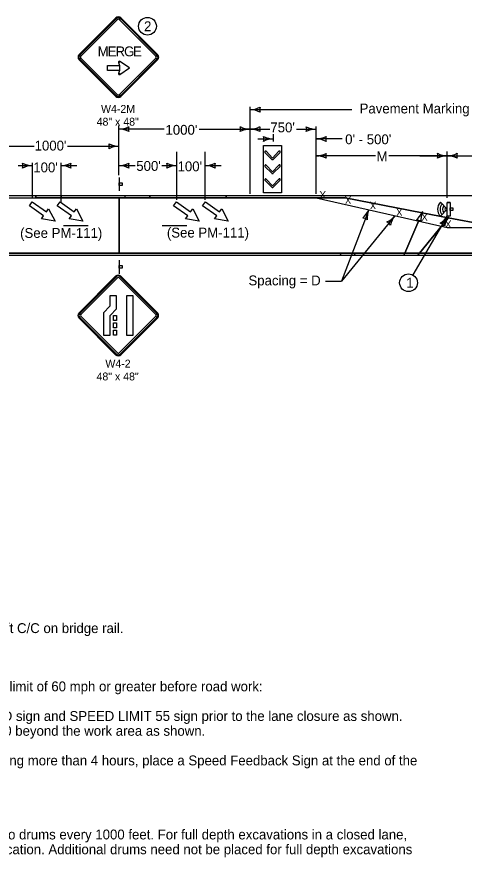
# Model space of a CAD drawing. Extents: x 10133 to 2270741, y 5363 to 1733450.
# Drawn here: x 25567 to 26474, y 5452 to 7155 of the extents above; entities that cross this region are included whole.
import ezdxf

# ---------------------------------------------------------------- set-up
doc = ezdxf.new("R2010")
doc.units = 0
for name, color, linetype in [('dsnNonPlotable', 7, 'Continuous'), ('dsnShtPlotShapeBatchPrint', 7, 'Continuous'), ('dsnStdBlockModified', 7, 'Continuous'), ('dsnStdBorder', 7, 'Continuous'), ('dsnStdNote', 7, 'Continuous'), ('dsnStdTable', 7, 'Continuous'), ('Level 12', 7, 'Continuous'), ('Level 2', 7, 'Continuous')]:
    doc.layers.add(name, color=color, linetype=linetype)

msp = doc.modelspace()

# ---------------------------------------------------------------- linework, layer by layer
at = {"layer": 'dsnNonPlotable'}
for p, q in [((24565.8, 6787.8), (26174.1, 6787.8)), ((25592.9, 6771.4), (25598.6, 6779.6)), ((25598.6, 6779.6), (25627.3, 6759.5)), ((25649.4, 6771.4), (25655.2, 6779.6)), ((25655.2, 6779.6), (25683.8, 6759.5)), ((25885.2, 6771.4), (25890.9, 6779.6)), ((25890.9, 6779.6), (25919.6, 6759.5)), ((25943.9, 6771.4), (25949.7, 6779.6)), ((25949.7, 6779.6), (25978.3, 6759.5)), ((26174.1, 6787.8), (26439.8, 6728.1)), ((25621.5, 6751.3), (25592.9, 6771.4)), ((25627.3, 6759.5), (25631.6, 6765.6)), ((25631.6, 6765.6), (25644.9, 6741)), ((25678.1, 6751.3), (25649.4, 6771.4)), ((25683.8, 6759.5), (25688.1, 6765.6)), ((25688.1, 6765.6), (25701.4, 6741)), ((25913.8, 6751.3), (25885.2, 6771.4)), ((25919.6, 6759.5), (25923.9, 6765.6)), ((25923.9, 6765.6), (25937.2, 6741)), ((25972.6, 6751.3), (25943.9, 6771.4)), ((25978.3, 6759.5), (25982.6, 6765.6)), ((25982.6, 6765.6), (25995.9, 6741)), ((25617.2, 6745.1), (25621.5, 6751.3)), ((25644.9, 6741), (25617.2, 6745.1)), ((25673.8, 6745.1), (25678.1, 6751.3)), ((25701.4, 6741), (25673.8, 6745.1)), ((25909.5, 6745.1), (25913.8, 6751.3)), ((25937.2, 6741), (25909.5, 6745.1)), ((25968.3, 6745.1), (25972.6, 6751.3)), ((25995.9, 6741), (25968.3, 6745.1)), ((26439.8, 6728.1), (26588, 6728.1)), ((24557.8, 6675.8), (26586.2, 6675.8))]:
    msp.add_line(p, q, dxfattribs=at)
for points in [[(25662, 6731.8), (25712, 6731.8)], [(25662, 6731.8), (25712, 6731.8)], [(25862, 6731.8), (25912, 6731.8)]]:
    msp.add_lwpolyline(points, dxfattribs=at)
at = {"layer": 'dsnShtPlotShapeBatchPrint'}
msp.add_circle((25832.2, 7135.5), 18, dxfattribs=at)
at = {"layer": 'dsnStdBlockModified'}
for p, q in [((26425.7, 6778.9), (26439.8, 6764.7)), ((26445.5, 6778.5), (26439.8, 6778.5)), ((26439.8, 6764.7), (26425.7, 6750.6)), ((26445.5, 6751), (26439.8, 6751))]:
    msp.add_line(p, q, dxfattribs=at)
for radius, start, end in [(20.3, 135.88, 224.0313), (15.3, 136.1665, 223.7159), (10.3, 136.7294, 223.0963), (5.32, 138.7005, 221.2995)]:
    msp.add_arc((26440.3, 6764.7), radius, start, end, dxfattribs=at)
at = {"layer": 'dsnStdBorder'}
for p, q in [((25767.9, 7152.4), (25693.7, 7078.2)), ((25769.3, 7151.1), (25771.5, 7148.9)), ((25775, 7148.9), (25777.2, 7151.1)), ((25852.8, 7078.2), (25778.5, 7152.4)), ((25693.7, 7067.6), (25767.9, 6993.3)), ((25697.2, 7074.7), (25695, 7076.9)), ((25695, 7068.9), (25697.2, 7071.1)), ((25778.5, 6993.3), (25852.8, 7067.6)), ((25851.5, 7076.9), (25849.2, 7074.7)), ((25849.2, 7071.1), (25851.5, 7068.9)), ((25773.3, 7061.9), (25775.3, 7062.6)), ((25775.3, 7062.6), (25776.3, 7064.3)), ((25775.3, 7039.5), (25773.3, 7040.1)), ((25776.3, 7037.7), (25775.3, 7039.5)), ((25771.5, 6996.9), (25769.3, 6994.7)), ((25777.2, 6994.7), (25775, 6996.9)), ((26086.8, 6865.8), (26100.9, 6879.9)), ((26086.8, 6837.6), (26100.9, 6851.7)), ((25775, 6829.3), (25775, 6801.8)), ((26086.8, 6809.5), (26100.9, 6823.6)), ((26445.5, 6778.5), (26445.5, 6751)), ((25775, 6661.8), (25775, 6634.3)), ((25693.5, 6555), (25767.7, 6629.3)), ((25767.7, 6629.3), (25693.5, 6555)), ((25694.8, 6553.7), (25769.1, 6628)), ((25771.3, 6625.8), (25697, 6551.5)), ((25767.7, 6629.3), (25767.7, 6629.3)), ((25771.3, 6625.8), (25771.3, 6625.8)), ((25849, 6551.5), (25774.8, 6625.8)), ((25777, 6628), (25851.3, 6553.7)), ((25778.3, 6629.3), (25852.6, 6555)), ((25852.6, 6555), (25778.3, 6629.3)), ((25767.7, 6470.2), (25693.5, 6544.4)), ((25693.5, 6544.4), (25767.7, 6470.2)), ((25769.1, 6471.5), (25694.8, 6545.8)), ((25697, 6548), (25771.3, 6473.7)), ((25774.8, 6473.7), (25849, 6548)), ((25851.3, 6545.8), (25777, 6471.5)), ((25852.6, 6544.4), (25778.3, 6470.2)), ((25778.3, 6470.2), (25852.6, 6544.4))]:
    msp.add_line(p, q, dxfattribs=at)
for points in [[(25769.3, 7151.1), (25695, 7076.9), (25697.2, 7074.7), (25771.5, 7148.9), (25769.3, 7151.1)], [(25851.5, 7076.9), (25777.2, 7151.1), (25775, 7148.9), (25849.2, 7074.7), (25851.5, 7076.9)], [(25695, 7068.9), (25769.3, 6994.7), (25771.5, 6996.9), (25697.2, 7071.1), (25695, 7068.9)], [(25777.2, 6994.7), (25851.5, 7068.9), (25849.2, 7071.1), (25775, 6996.9), (25777.2, 6994.7)], [(25750.9, 7046), (25750.9, 7056), (25775.3, 7056), (25775.3, 7046), (25750.9, 7046)], [(25795.6, 7051), (25776.3, 7064.3), (25775.3, 7062.6), (25773.3, 7061.9), (25775.3, 7056), (25775.3, 7046), (25773.3, 7040.1), (25775.3, 7039.5), (25776.3, 7037.7), (25795.6, 7051)], [(26104, 6894), (26104, 6798), (26067.3, 6798), (26067.3, 6894)], [(25775.1, 6812.9), (25775.1, 6818.5), (25780.8, 6818.5), (25780.8, 6812.9)], [(26439.8, 6751), (26439.8, 6778.5), (26445.5, 6778.5), (26445.5, 6751)], [(26445.5, 6762), (26445.5, 6767.7), (26451.1, 6767.7), (26451.1, 6762)], [(25775.1, 6645.4), (25775.1, 6651), (25780.8, 6651), (25780.8, 6645.4)], [(25756, 6568.6), (25742.8, 6555.3), (25742.8, 6509.7), (25756.3, 6509.7), (25756.3, 6549.7), (25769.5, 6563), (25769.5, 6589.7), (25756, 6589.7)], [(25789.8, 6589.7), (25789.8, 6509.7), (25803.3, 6509.7), (25803.3, 6589.7)], [(25763.5, 6549.7), (25769.5, 6549.7), (25769.5, 6539.7), (25763.5, 6539.7)], [(25763.5, 6534.7), (25769.5, 6534.7), (25769.5, 6524.7), (25763.5, 6524.7)], [(25763.5, 6519.7), (25769.5, 6519.7), (25769.5, 6509.7), (25763.5, 6509.7)]]:
    msp.add_lwpolyline(points, close=True, dxfattribs=at)
for points in [[(26070.3, 6880), (26070.3, 6879.9), (26084.4, 6865.8), (26084.4, 6865.8)], [(26098.6, 6882.3), (26098.5, 6882.2), (26085.6, 6868.6), (26072.7, 6882.2)], [(26070.3, 6851.7), (26070.3, 6851.7), (26084.4, 6837.6), (26084.4, 6837.6)], [(26098.6, 6854), (26098.5, 6854), (26085.6, 6840.4), (26072.7, 6854)], [(26070.3, 6823.7), (26070.3, 6823.6), (26084.4, 6809.5), (26084.4, 6809.5)], [(26098.6, 6826), (26098.5, 6825.9), (26085.6, 6812.3), (26072.7, 6825.9)], [(25769.1, 6628), (25694.8, 6553.7)], [(25771.3, 6625.8), (25697, 6551.5)], [(25849, 6551.5), (25774.8, 6625.8)], [(25851.3, 6553.7), (25777, 6628)], [(25694.8, 6545.8), (25769.1, 6471.5)], [(25697, 6548), (25771.3, 6473.7)], [(25774.8, 6473.7), (25849, 6548)], [(25777, 6471.5), (25851.3, 6545.8)]]:
    msp.add_lwpolyline(points, dxfattribs=at)
for centre, radius, start, end in [((25773.2, 7147.1), 7.5, 45, 134.9997), ((25773.2, 7147.1), 5.62, 45, 134.9997), ((25773.2, 7147.1), 2.5, 45, 134.9997), ((25699, 7072.9), 7.5, 134.9997, 225), ((25699, 7072.9), 5.62, 134.9997, 225), ((25699, 7072.9), 2.5, 134.9997, 225), ((25847.5, 7072.9), 2.5, 315.0002, 44.9998), ((25847.5, 7072.9), 5.62, 315.0002, 44.9998), ((25847.5, 7072.9), 7.5, 315.0002, 44.9998), ((25775.3, 7062.6), 2.03, 57.6877, 198.5814), ((25775.3, 7039.5), 2.03, 161.4183, 302.3126), ((25773.2, 6998.6), 2.5, 225, 315.0002), ((25773.2, 6998.6), 7.5, 225, 315.0002), ((25773.2, 6998.6), 5.62, 225, 315.0002), ((26071.5, 6881.1), 1.65, 42.6398, 223.799), ((26099.7, 6881.1), 1.65, 314.719, 134.9025), ((26085.6, 6867), 1.65, 225.3902, 315.8384), ((26071.5, 6852.9), 1.65, 42.6398, 223.799), ((26099.7, 6852.9), 1.65, 314.719, 134.9025), ((26071.5, 6824.8), 1.65, 42.6398, 223.799), ((26085.6, 6838.7), 1.65, 225.3902, 315.8384), ((26099.7, 6824.8), 1.65, 314.719, 134.9025), ((26085.6, 6810.7), 1.65, 225.3902, 315.8384), ((25773, 6624), 7.5, 45.0003, 135), ((25773, 6624), 7.5, 45.0003, 135), ((25773, 6624), 5.63, 45.0003, 135), ((25773, 6624), 5.63, 45.0003, 135), ((25773, 6624), 2.5, 45.0003, 135), ((25773, 6624), 2.5, 45.0003, 135), ((25698.8, 6549.7), 7.5, 135.0002, 224.9998), ((25698.8, 6549.7), 7.5, 135.0002, 224.9998), ((25847.3, 6549.7), 7.5, 315, 45.0003), ((25847.3, 6549.7), 7.5, 315, 45.0003), ((25698.8, 6549.7), 5.63, 135.0002, 224.9998), ((25698.8, 6549.7), 5.63, 135.0002, 224.9998), ((25698.8, 6549.7), 2.5, 135.0002, 224.9998), ((25698.8, 6549.7), 2.5, 135.0002, 224.9998), ((25847.3, 6549.7), 2.5, 315, 45.0003), ((25847.3, 6549.7), 2.5, 315, 45.0003), ((25847.3, 6549.7), 5.63, 315, 45.0003), ((25847.3, 6549.7), 5.63, 315, 45.0003), ((25773, 6475.5), 7.5, 224.9998, 315), ((25773, 6475.5), 7.5, 224.9998, 315), ((25773, 6475.5), 5.63, 224.9998, 315), ((25773, 6475.5), 5.63, 224.9998, 315), ((25773, 6475.5), 2.5, 224.9998, 315), ((25773, 6475.5), 2.5, 224.9998, 315)]:
    msp.add_arc(centre, radius, start, end, dxfattribs=at)
at = {"layer": 'dsnStdNote'}
msp.add_circle((26361.2, 6615.9), 18, dxfattribs=at)
at = {"layer": 'Level 12'}
for p, q in [((26040.2, 6796), (26040.2, 6972.6)), ((26246.2, 6966.5), (26040.2, 6966.5)), ((25774.4, 6833.6), (25774.4, 6934.2)), ((26174.1, 6796), (26174.1, 6932.7)), ((25866, 6927.1), (25774.4, 6927.1)), ((25937.2, 6927.1), (26040.2, 6927.1)), ((26040.2, 6927.1), (26080.2, 6927.1)), ((26087.5, 6902), (26087.5, 6916.8)), ((26134.1, 6927.1), (26174.1, 6927.1)), ((26055.5, 6907.3), (26087.5, 6907.3)), ((26226.5, 6907.2), (26174.1, 6907.2)), ((25482.1, 6892.4), (25602.8, 6892.4)), ((25670.4, 6892.4), (25774.4, 6892.4)), ((25891.6, 6784.2), (25891.6, 6881.1)), ((25949.4, 6784.2), (25949.4, 6881.1)), ((26439.8, 6788.1), (26439.8, 6881.6)), ((26294.1, 6873), (26174.1, 6873)), ((26441.6, 6873.1), (26321.6, 6873.1)), ((26384.2, 6873.1), (26501.1, 6873.1)), ((25570.3, 6853.2), (25598.9, 6853.2)), ((25598.9, 6787.6), (25598.9, 6858.8)), ((25657.1, 6779.4), (25657.1, 6858.8)), ((25657.1, 6853.2), (25689.1, 6853.2)), ((25775.2, 6853.2), (25807.1, 6853.2)), ((25861.5, 6853.2), (25891.6, 6853.2)), ((25949.4, 6853.2), (25981.4, 6853.2)), ((26280.6, 6763.6), (26225.1, 6619.1)), ((26333.4, 6751.6), (26225.1, 6619.1)), ((26439.8, 6751), (26369.8, 6631.7)), ((26193.1, 6619.1), (26225.1, 6619.1))]:
    msp.add_line(p, q, dxfattribs=at)
for centre, radius, start, end in [((26040.2, 7009), 42.5, 270, 298.0725), ((26040.2, 6924), 42.5, 61.9275, 90), ((26075.9, 6966.5), 16.4, 162.2666, 197.7334), ((25774.4, 6969.6), 42.5, 270, 298.0725), ((25810, 6927.1), 16.4, 162.2666, 197.7334), ((26004.6, 6927.1), 16.4, 342.2666, 17.7334), ((26040.2, 6969.6), 42.5, 241.9275, 270), ((26040.2, 6969.6), 42.5, 270, 298.0725), ((26075.8, 6927.1), 16.4, 162.2666, 197.7334), ((26138.4, 6927), 16.4, 342.2666, 17.7334), ((26174.1, 6969.5), 42.5, 241.9275, 270), ((25774.4, 6884.6), 42.5, 61.9275, 90), ((26040.2, 6884.6), 42.5, 90, 118.0725), ((26040.2, 6884.6), 42.5, 61.9275, 90), ((26051.9, 6907.3), 16.4, 342.2666, 17.7334), ((26087.5, 6949.8), 42.5, 241.9275, 270), ((26174.1, 6884.5), 42.5, 90, 118.0725), ((26174.1, 6949.7), 42.5, 270, 298.0725), ((26209.7, 6907.2), 16.4, 162.2666, 197.7334), ((25738.7, 6892.4), 16.4, 342.2666, 17.7334), ((25774.4, 6934.9), 42.5, 241.9275, 270), ((26087.5, 6864.8), 42.5, 90, 118.0725), ((26174.1, 6864.7), 42.5, 61.9275, 90), ((25774.4, 6849.9), 42.5, 90, 118.0725), ((26174.1, 6915.5), 42.5, 270, 298.0725), ((26209.7, 6873), 16.4, 162.2666, 197.7334), ((26404.2, 6873.1), 16.4, 342.2666, 17.7334), ((26439.8, 6915.6), 42.5, 241.9275, 270), ((26439.8, 6915.6), 42.5, 270, 298.0725), ((26475.5, 6873.1), 16.4, 162.2666, 197.7334), ((26174.1, 6830.5), 42.5, 61.9275, 90), ((26439.8, 6830.6), 42.5, 90, 118.0725), ((26439.8, 6830.6), 42.5, 61.9275, 90), ((25563.3, 6853.2), 16.4, 342.2666, 17.7334), ((25598.9, 6895.7), 42.5, 241.9275, 270), ((25598.9, 6810.7), 42.5, 90, 118.0725), ((25657.1, 6895.7), 42.5, 270, 298.0725), ((25657.1, 6810.7), 42.5, 61.9275, 90), ((25692.7, 6853.2), 16.4, 162.2666, 197.7334), ((25774.6, 6895.7), 42.5, 270, 298.0725), ((25774.6, 6810.7), 42.5, 61.9275, 90), ((25810.2, 6853.2), 16.4, 162.2666, 197.7334), ((25855.9, 6853.2), 16.4, 342.2666, 17.7334), ((25891.6, 6895.7), 42.5, 241.9275, 270), ((25891.6, 6810.7), 42.5, 90, 118.0725), ((25949.4, 6895.7), 42.5, 270, 298.0725), ((25949.4, 6810.7), 42.5, 61.9275, 90), ((25985, 6853.2), 16.4, 162.2666, 197.7334), ((26241.4, 6780), 42.5, 309.2655, 337.338), ((26319.8, 6747.2), 42.5, 157.338, 185.4105), ((26266.9, 6730.7), 16.4, 49.6046, 85.0713), ((26300.2, 6778.1), 42.5, 293.3393, 321.4118), ((26366.6, 6725.1), 42.5, 141.4118, 169.4842), ((26403.6, 6773.3), 42.5, 300.2855, 328.358), ((26476, 6728.7), 42.5, 148.358, 176.4305), ((26311.2, 6723.8), 16.4, 33.6784, 69.1451), ((26421.1, 6720.7), 16.4, 40.6246, 76.0913)]:
    msp.add_arc(centre, radius, start, end, dxfattribs=at)
at = {"layer": 'Level 2'}
for p, q in [((25606.3, 6791.8), (24561.8, 6791.8)), ((25598.9, 6791.8), (24561.8, 6791.8)), ((24565.8, 6787.8), (25598.9, 6787.8)), ((25598.9, 6787.8), (25598.9, 6791.8)), ((25606.3, 6787.8), (25606.3, 6791.8)), ((25657.1, 6791.8), (25606.3, 6791.8)), ((25606.3, 6791.8), (25606.3, 6787.8)), ((25606.3, 6787.8), (25657.1, 6787.8)), ((25891.6, 6791.8), (25657.1, 6791.8)), ((25657.1, 6791.8), (25657.1, 6787.8)), ((25657.1, 6787.8), (25657.1, 6791.8)), ((25657.1, 6787.8), (25891.6, 6787.8)), ((25775, 6675.8), (25775, 6787.8)), ((25836.9, 6787.8), (25775, 6787.8)), ((25775, 6787.8), (25775, 6675.8)), ((25836.9, 6791.8), (25786.1, 6791.8)), ((25786.1, 6791.8), (25786.1, 6787.8)), ((25786.1, 6787.8), (25836.9, 6787.8)), ((25991.5, 6791.8), (25836.9, 6791.8)), ((25836.9, 6791.8), (25836.9, 6787.8)), ((25836.9, 6787.8), (25836.9, 6791.8)), ((25991.5, 6791.8), (25836.9, 6791.8)), ((25836.9, 6791.8), (25836.9, 6787.8)), ((25836.9, 6787.8), (25991.5, 6787.8)), ((25836.9, 6787.8), (25991.5, 6787.8)), ((25991.5, 6787.8), (25836.9, 6787.8)), ((25891.6, 6787.8), (25891.6, 6791.8)), ((25991.5, 6787.8), (25991.5, 6791.8)), ((25991.5, 6787.8), (25991.5, 6791.8)), ((26822.2, 6791.8), (25991.5, 6791.8)), ((25991.5, 6791.8), (25991.5, 6787.8)), ((26232.5, 6787.8), (25991.5, 6787.8)), ((25991.5, 6787.8), (26232.5, 6787.8)), ((26388.6, 6757.8), (26232.5, 6787.8)), ((26232.5, 6787.8), (26388.6, 6757.8)), ((26353.4, 6675.8), (26382, 6742.3)), ((26382, 6742.3), (26353.4, 6675.8)), ((26388.8, 6757.8), (26441.5, 6747.6)), ((26441.5, 6747.6), (26388.8, 6757.8)), ((26441.6, 6747.6), (26543.1, 6728.1)), ((26543.1, 6728.1), (26441.6, 6747.6)), ((26383.4, 6675.8), (26430.6, 6734.2)), ((26430.6, 6734.2), (26383.4, 6675.8)), ((26353.4, 6675.8), (24557.8, 6675.8)), ((24557.8, 6675.8), (25775, 6675.8)), ((25775, 6675.8), (26353.4, 6675.8)), ((26224.1, 6675.8), (26222.5, 6671.8)), ((26254.2, 6675.8), (26224.1, 6675.8)), ((26251.1, 6671.8), (26254.2, 6675.8)), ((26351.6, 6671.8), (26353.4, 6675.8)), ((26353.4, 6675.8), (26351.6, 6671.8)), ((26383.4, 6675.8), (26353.4, 6675.8)), ((26353.4, 6675.8), (26383.4, 6675.8)), ((26383.4, 6675.8), (26380.1, 6671.8)), ((26380.1, 6671.8), (26383.4, 6675.8)), ((26619.6, 6675.8), (26383.4, 6675.8)), ((24561.8, 6671.8), (26380.1, 6671.8)), ((24561.8, 6671.8), (26351.6, 6671.8)), ((26222.5, 6671.8), (26251.1, 6671.8)), ((26351.6, 6671.8), (26380.1, 6671.8)), ((26380.1, 6671.8), (26616.7, 6671.8))]:
    msp.add_line(p, q, dxfattribs=at)
for points in [[(25775, 6787.8), (25657.1, 6787.8), (25606.3, 6787.8)], [(26389.2, 6759.1), (26389.6, 6760), (26389.6, 6760)], [(26389.3, 6759.1), (26389.2, 6759.1)], [(26441.6, 6747.6), (26441.5, 6747.6)], [(26442.3, 6748.6), (26442.7, 6749.1), (26442.7, 6749.1)], [(26383.4, 6675.8), (26592.2, 6675.8), (26687.2, 6675.8)]]:
    msp.add_lwpolyline(points, dxfattribs=at)
for centre, radius, start, end in [((26350.4, 6776.4), 42.5, 309.2655, 336.072), ((26350.4, 6776.4), 42.5, 334.0959, 336.072), ((26428.8, 6743.6), 42.5, 157.3556, 160.5422), ((26428.8, 6743.6), 42.5, 158.6034, 160.5422), ((26350.4, 6776.4), 42.5, 337.3204, 337.338), ((26350.4, 6776.4), 42.5, 309.2655, 334.0959), ((26375.9, 6727.1), 16.4, 68.0792, 85.0713), ((26375.9, 6727.1), 16.4, 49.6046, 85.0713), ((26375.9, 6727.1), 16.4, 49.6046, 68.0792), ((26428.8, 6743.6), 42.5, 160.5422, 185.4105), ((26428.8, 6743.6), 42.5, 160.5422, 185.4105), ((26409.5, 6775.6), 42.5, 293.3393, 318.8219), ((26409.5, 6775.6), 42.5, 293.3393, 318.8219), ((26476, 6722.6), 42.5, 143.9415, 169.4842), ((26476, 6722.6), 42.5, 143.9415, 169.4842), ((26409.5, 6775.6), 42.5, 318.8219, 320.5615), ((26476, 6722.6), 42.5, 141.4294, 143.9415), ((26409.5, 6775.6), 42.5, 321.3942, 321.4118), ((26420.5, 6721.2), 16.4, 51.9095, 69.1451), ((26420.5, 6721.2), 16.4, 33.6784, 69.1451), ((26420.5, 6721.2), 16.4, 33.6784, 51.9095)]:
    msp.add_arc(centre, radius, start, end, dxfattribs=at)

# ---------------------------------------------------------------- texts
at = {"layer": 'dsnShtPlotShapeBatchPrint'}
msp.add_text('2', height=20, dxfattribs=at).set_placement((25825.2, 7125.5))
at = {"layer": 'dsnStdBorder'}
for s, height, p in [('M', 20, (25731.3, 7074.6)), ('E', 20, (25751.6, 7074.6)), ('R', 20, (25767.5, 7074.6)), ('G', 20, (25784.8, 7074.6)), ('E', 20, (25802.9, 7074.6)), ('W4-2M', 16, (25738.1, 6960.1)), ('48" x 48"', 16, (25729.2, 6934.1)), ('(See PM-111)', 20, (25574.1, 6706.8)), ('(See PM-111)', 20, (25871.5, 6707.5)), ('W4-2', 16, (25746.9, 6444.1)), ('48" x 48"', 16, (25729, 6418.1))]:
    msp.add_text(s, height=height, dxfattribs=at).set_placement(p)
for p in [(26194, 6801.9), (26245.4, 6791.1), (26295.9, 6780), (26349.4, 6766.7), (26400.5, 6756.7), (26448.3, 6742.5)]:
    msp.add_text('X', height=15, rotation=180, dxfattribs=at).set_placement(p)
at = {"layer": 'dsnStdNote'}
msp.add_text('1', height=20, dxfattribs=at).set_placement((26356.5, 6605.9))
at = {"layer": 'dsnStdTable'}
for s, p in [('Place Concrete Barrier Markers at 10 ft C/C on bridge rail.', (25096.7, 5906.3)), ('For roadways with a posted speed limit of 60 mph or greater before road work:', (25137.9, 5788.3)), ('Place SPEED LIMIT AHEAD sign and SPEED LIMIT 55 sign prior to the lane closure as shown. ', (25217.9, 5728.3)), ('Place SPEED LIMIT65 or 70 beyond the work area as shown.', (25217.9, 5698.3)), ('For traffic control zones lasting more than 4 hours, place a Speed Feedback Sign at the end of the ', (25217.9, 5638.3)), ('For lanes closed to traffic, place two drums every 1000 feet. For full depth excavations in a closed lane, ', (25137.9, 5488.3)), ('place two drums in front of each location. Additional drums need not be placed for full depth excavations ', (25137.9, 5458.3))]:
    msp.add_text(s, height=20, dxfattribs=at).set_placement(p)
at = {"layer": 'Level 12'}
for s, p in [('Pavement Marking Removal Limits', (26262, 6958.9)), ("1000'", (25868.7, 6915.7)), ("750'", (26081.2, 6920.6)), ("0' - 500'", (26232.8, 6896.5)), ("1000'", (25603.5, 6883.7)), ('M', (26296.4, 6861.8)), ("500'", (25809.5, 6842.5)), ("100'", (25893.2, 6841.7)), ("100'", (25600.8, 6839.6)), ('Spacing = D', (26036.8, 6610.6))]:
    msp.add_text(s, height=20, dxfattribs=at).set_placement(p)

doc.saveas('drawing.dxf')
